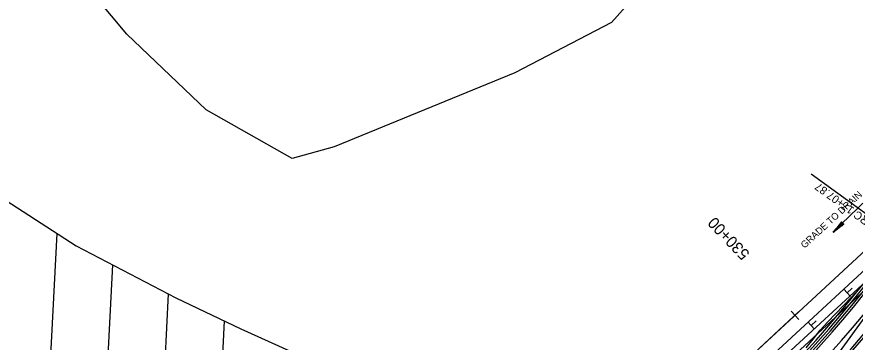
# Model space of a CAD drawing. Extents: x 1300404 to 1323571, y 234004 to 252077.
# Drawn here: x 1310836 to 1311569, y 242157 to 242442 of the extents above; entities that cross this region are included whole.
import ezdxf

# ---------------------------------------------------------------- set-up
doc = ezdxf.new("R2010")
doc.units = 0
for name, color, linetype in [('R_Barrel', 7, 'Continuous'), ('R_Const Limits', 7, 'Continuous'), ('R_Floodway', 7, 'Continuous'), ('R_Flooplain', 7, 'Continuous'), ('R_Flow Arrows', 7, 'Continuous'), ('R_Horz Alg Major Ticks', 7, 'Continuous'), ('R_Horz Alg Station Annot', 7, 'Continuous'), ('R_Lane Edge', 7, 'Continuous'), ('R_MOT Proposed', 7, 'Continuous'), ('R_No Plot', 7, 'Continuous'), ('R_Proposed', 7, 'Continuous'), ('R_Shoulder', 7, 'Continuous')]:
    doc.layers.add(name, color=color, linetype=linetype)

msp = doc.modelspace()

# ---------------------------------------------------------------- linework, layer by layer
at = {"layer": 'R_Barrel'}
for p, q in [((1311564.84, 242197.14), (1311558.99, 242203.45)), ((1311561.93, 242200.28), (1311566.33, 242204.36)), ((1311533.32, 242168.49), (1311527.48, 242174.8)), ((1311530.41, 242171.63), (1311534.81, 242175.71))]:
    msp.add_line(p, q, dxfattribs=at)
at = {"layer": 'R_Const Limits'}
msp.add_line((1311459.91, 242094.38), (1311606.87, 242230.04), dxfattribs=at)
at = {"layer": 'R_Floodway'}
for p, q in [((1310845.63, 241748), (1310870.89, 242252.19)), ((1310894.59, 241726), (1310919.58, 242224.73)), ((1310943.55, 241703.99), (1310968.37, 242199.27)), ((1310992.51, 241681.98), (1311017.25, 242175.67))]:
    msp.add_line(p, q, dxfattribs=at)
msp.add_lwpolyline([(1310244.92, 242890.78), (1310303.34, 242800.73), (1310379.63, 242680.75), (1310490.18, 242568.72), (1310548.96, 242534.3), (1310676.05, 242414.18), (1310731.56, 242362.99), (1310810.26, 242291.28), (1310887.62, 242241.41), (1310974.87, 242195.88), (1311031.59, 242168.82), (1311109.67, 242133.43), (1311173.76, 242108.43), (1311242.66, 242083.18), (1311339.33, 242032.34), (1311351.04, 242024.49), (1311431.54, 241940.59), (1311405.15, 241750.77), (1311416.02, 241677.63), (1311441.14, 241598.94), (1311547.83, 241506.46)], dxfattribs=at)
at = {"layer": 'R_Flooplain'}
for p, q in [((1310931.93, 242426.69), (1310877.13, 242492.36)), ((1311376.36, 242459.95), (1311355.85, 242436.79)), ((1311355.85, 242436.79), (1311271.39, 242392.65)), ((1311001.21, 242360.29), (1310931.93, 242426.69)), ((1311271.39, 242392.65), (1311113.32, 242328.03)), ((1311076.52, 242317.78), (1311001.21, 242360.29)), ((1311113.32, 242328.03), (1311076.52, 242317.78))]:
    msp.add_line(p, q, dxfattribs=at)
at = {"layer": 'R_Flow Arrows'}
for p, q in [((1311556.91, 242262.45), (1311549.61, 242253.12)), ((1311559.04, 242260.29), (1311556.91, 242262.45)), ((1311559.04, 242260.29), (1311549.61, 242253.12))]:
    msp.add_line(p, q, dxfattribs=at)
for points in [[(1311575.74, 242278.59), (1311571.61, 242274.57), (1311549.5, 242253.23)], [(1311557.12, 242262.24), (1311555.45, 242260.59)], [(1311557.76, 242261.59), (1311553.33, 242257.22), (1311551.06, 242254.99)], [(1311558.19, 242261.15), (1311553.76, 242256.79), (1311551.49, 242254.56)], [(1311557.55, 242261.8), (1311553.12, 242257.44), (1311552.53, 242256.86)], [(1311558.4, 242260.94), (1311553.97, 242256.57), (1311553.38, 242255.99)], [(1311557.33, 242262.02), (1311553.99, 242258.72)], [(1311558.61, 242260.72), (1311555.27, 242257.42)], [(1311558.83, 242260.5), (1311557.15, 242258.85)]]:
    msp.add_lwpolyline(points, dxfattribs=at)
at = {"layer": 'R_Horz Alg Major Ticks'}
msp.add_lwpolyline([(1311512.93, 242184.34), (1311519.72, 242177)], dxfattribs=at)
msp.add_lwpolyline([(1311512.93, 242184.34), (1311519.72, 242177)], dxfattribs=at)
at = {"layer": 'R_Lane Edge'}
msp.add_line((1311451.09, 242103.93), (1311598.05, 242239.59), dxfattribs=at)
at = {"layer": 'R_MOT Proposed'}
msp.add_line((1311481.76, 242046.92), (1311620.62, 242238.62), dxfattribs=at)
msp.add_lwpolyline([(1311620.62, 242238.62), (1311530.42, 242303.96)], dxfattribs=at)
msp.add_arc((1310692.59, 242910.85), 1145.92, 300.73904, 324.0818, dxfattribs=at)
at = {"layer": 'R_No Plot'}
msp.add_lwpolyline([(1311525.97, 242152.22), (1311532.21, 242159.84), (1311538.31, 242167.57), (1311544.98, 242174.79), (1311551.82, 242181.87), (1311558.59, 242189.03), (1311565.31, 242196.24), (1311571.97, 242203.52)], dxfattribs=at)
for radius, end in [(1128.92, 324.0818), (1130.92, 324.08626), (1132.92, 324.0818), (1134.92, 324.0818), (1156.92, 324.0818), (1158.92, 324.0818)]:
    msp.add_arc((1310692.59, 242910.85), radius, 300.73904, end, dxfattribs=at)
at = {"layer": 'R_Proposed'}
for p, q in [((1311366.68, 242042.15), (1311589.71, 242248.6)), ((1311366.68, 242042.15), (1311589.71, 242248.6)), ((1311519.37, 242183.49), (1311366.68, 242042.15)), ((1311366.68, 242042.15), (1311519.37, 242183.49)), ((1311366.68, 242042.15), (1311519.37, 242183.49)), ((1311519.37, 242183.49), (1311366.68, 242042.15)), ((1311366.68, 242042.15), (1311519.37, 242183.49)), ((1311366.68, 242042.15), (1311519.37, 242183.49))]:
    msp.add_line(p, q, dxfattribs=at)
at = {"layer": 'R_Shoulder'}
msp.add_line((1311456.52, 242098.06), (1311603.48, 242233.71), dxfattribs=at)

# ---------------------------------------------------------------- texts
at = {"layer": 'R_Flow Arrows'}
msp.add_text('GRADE TO DRAIN', height=6, rotation=42.53191, dxfattribs=at).set_placement((1311524.63, 242238.79))
at = {"layer": 'R_Horz Alg Station Annot'}
msp.add_text('530+00', height=10, rotation=133.51022, dxfattribs=at).set_placement((1311477.31, 242234.84))
at = {"layer": 'R_MOT Proposed'}
msp.add_text('PRC 17+07.87', height=7, rotation=144.0818, dxfattribs=at).set_placement((1311586.83, 242260.99))

doc.saveas('drawing.dxf')
